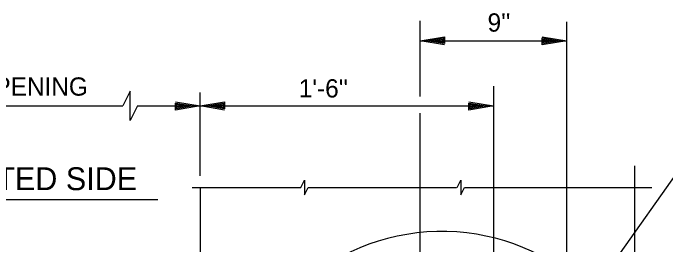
# Model space of a CAD drawing. Extents: x 18232 to 22378, y 12454 to 22381.
# Drawn here: x 22373.245 to 22376.583, y 22379.554 to 22380.738 of the extents above; entities that cross this region are included whole.
import ezdxf

# ---------------------------------------------------------------- set-up
doc = ezdxf.new("R2010")
doc.units = 0
for name, color, linetype in [('Level 1', 7, 'Continuous'), ('Level 2', 7, 'Continuous'), ('Level 3', 7, 'Continuous')]:
    doc.layers.add(name, color=color, linetype=linetype)

msp = doc.modelspace()

# ---------------------------------------------------------------- linework, layer by layer
at = {"layer": 'Level 1'}
for points in [[(22373.8805, 22380.2633), (22373.8433, 22380.1883), (22373.8433, 22380.3381), (22373.8058, 22380.2633)], [(22374.7158, 22379.8466), (22374.7344, 22379.8841), (22374.7344, 22379.8092), (22374.7532, 22379.8466)], [(22375.5165, 22379.8466), (22375.5351, 22379.8841), (22375.5351, 22379.8092), (22375.5538, 22379.8466)]]:
    msp.add_lwpolyline(points, dxfattribs=at)
at = {"layer": 'Level 2'}
for p, q in [((22375.3259, 22380.5966), (22376.0759, 22380.5966)), ((22374.2009, 22380.2633), (22375.7009, 22380.2633)), ((22376.4247, 22379.4395), (22376.4247, 22379.9573)), ((22374.1603, 22379.8466), (22374.7158, 22379.8466)), ((22374.7532, 22379.8466), (22375.5118, 22379.8466)), ((22375.5538, 22379.8466), (22376.5112, 22379.8466))]:
    msp.add_line(p, q, dxfattribs=at)
at = {"layer": 'Level 3'}
for p, q in [((22375.3259, 22380.3114), (22375.3259, 22380.6976)), ((22376.0759, 22379.1841), (22376.0759, 22380.6931)), ((22375.3259, 22380.5966), (22375.3259, 22380.5966)), ((22375.3605, 22380.5966), (22375.3605, 22380.5966)), ((22376.0412, 22380.5966), (22376.0412, 22380.5966)), ((22376.0759, 22380.5966), (22376.0759, 22380.5966)), ((22375.7009, 22380.3652), (22375.7009, 22377.2902)), ((22374.2009, 22379.9059), (22374.2009, 22380.3326)), ((22372.2389, 22380.2633), (22373.8058, 22380.2633)), ((22373.8805, 22380.2633), (22374.2009, 22380.2633)), ((22374.1662, 22380.2633), (22374.1662, 22380.2633)), ((22374.2009, 22380.2633), (22374.2009, 22380.2633)), ((22374.2009, 22380.2633), (22374.2009, 22380.2633)), ((22374.2355, 22380.2633), (22374.2355, 22380.2633)), ((22375.6662, 22380.2633), (22375.6662, 22380.2633)), ((22375.7009, 22380.2633), (22375.7009, 22380.2633)), ((22375.3259, 22379.0264), (22375.3259, 22380.226)), ((22375.9647, 22378.9691), (22376.7333, 22380.0543)), ((22374.2009, 22379.8466), (22374.2009, 22378.9691)), ((22372.4641, 22379.7855), (22373.986, 22379.7855))]:
    msp.add_line(p, q, dxfattribs=at)
for points in [[(22375.4505, 22380.5759), (22375.3259, 22380.5966), (22375.4505, 22380.6173), (22375.4505, 22380.5819), (22375.3605, 22380.5966), (22375.4452, 22380.6106), (22375.4452, 22380.5879), (22375.3939, 22380.5966), (22375.4399, 22380.6039), (22375.4399, 22380.5946), (22375.4285, 22380.5966)], [(22375.9512, 22380.6173), (22376.0759, 22380.5966), (22375.9512, 22380.5759), (22375.9512, 22380.6113), (22376.0412, 22380.5966), (22375.9565, 22380.5826), (22375.9565, 22380.6053), (22376.0079, 22380.5966), (22375.9619, 22380.5893), (22375.9619, 22380.5986), (22375.9732, 22380.5966)], [(22374.0762, 22380.2839), (22374.2009, 22380.2633), (22374.0762, 22380.2426), (22374.0762, 22380.2779), (22374.1662, 22380.2633), (22374.0815, 22380.2493), (22374.0815, 22380.2719), (22374.1329, 22380.2633), (22374.0869, 22380.2559), (22374.0869, 22380.2653), (22374.0982, 22380.2633)], [(22374.3255, 22380.2426), (22374.2009, 22380.2633), (22374.3255, 22380.2839), (22374.3255, 22380.2486), (22374.2355, 22380.2633), (22374.3202, 22380.2773), (22374.3202, 22380.2546), (22374.2689, 22380.2633), (22374.3149, 22380.2706), (22374.3149, 22380.2613), (22374.3035, 22380.2633)], [(22375.5762, 22380.2839), (22375.7009, 22380.2633), (22375.5762, 22380.2426), (22375.5762, 22380.2779), (22375.6662, 22380.2633), (22375.5815, 22380.2493), (22375.5815, 22380.2719), (22375.6329, 22380.2633), (22375.5869, 22380.2559), (22375.5869, 22380.2653), (22375.5982, 22380.2633)]]:
    msp.add_lwpolyline(points, dxfattribs=at)
msp.add_arc((22375.4378, 22378.5278), 1.0946, 287.7103, 177.2166, dxfattribs=at)

# ---------------------------------------------------------------- texts
for s, height, p in [("9''", 0.09333, (22375.6713, 22380.6431)), ("64'-0'' OPENING", 0.093167, (22372.6976, 22380.3161)), ("1'-6''", 0.09333, (22374.706, 22380.3067)), ('PROTECTED SIDE', 0.116792, (22372.5082, 22379.8333))]:
    msp.add_text(s, height=height, dxfattribs=at).set_placement(p)

doc.saveas('drawing.dxf')
